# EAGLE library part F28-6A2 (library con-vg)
CONNECTOR female, 28 pins + 6 high current, type C
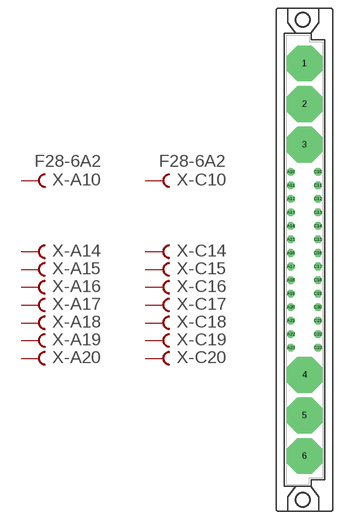
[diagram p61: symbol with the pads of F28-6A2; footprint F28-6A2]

Designator prefix X; gates -A10=FVAL -A14=FEM -A15=FEM -A16=FEM -A17=FEM -A18=FEM -A19=FEM -A20=FEM -C10=FVAL -C14=FEM -C15=FEM -C16=FEM -C17=FEM -C18=FEM -C19=FEM -C20=FEM -A21=FEM -A22=FEM -A23=FEM -C21=FEM -C22=FEM -C23=FEM -1=FEM-HIGHCUR -2=FEM-HIGHCUR -3=FEM-HIGHCUR -4=FEM-HIGHCUR -5=FEM-HIGHCUR -6=FEM-HIGHCUR -A11=FEM -A12=FEM -A13=FEM -C11=FEM -C12=FEM -C13=FEM

## F28-6A2  [F28-6A2]
1  -1:B  pas
2  -2:B  pas
3  -3:B  pas
4  -4:B  pas
5  -5:B  pas
6  -6:B  pas
A10  -A10:B  pas
A11  -A11:B  pas
A12  -A12:B  pas
A13  -A13:B  pas
A14  -A14:B  pas
A15  -A15:B  pas
A16  -A16:B  pas
A17  -A17:B  pas
A18  -A18:B  pas
A19  -A19:B  pas
A20  -A20:B  pas
A21  -A21:B  pas
A22  -A22:B  pas
A23  -A23:B  pas
C10  -C10:B  pas
C11  -C11:B  pas
C12  -C12:B  pas
C13  -C13:B  pas
C14  -C14:B  pas
C15  -C15:B  pas
C16  -C16:B  pas
C17  -C17:B  pas
C18  -C18:B  pas
C19  -C19:B  pas
C20  -C20:B  pas
C21  -C21:B  pas
C22  -C22:B  pas
C23  -C23:B  pas

## Footprint F28-6A2 (pad centres in mm)
CONNECTOR female, 28 pins + 6 high current, type C
drill 5.7 octagon: 1 0,36.83; 2 0,29.21; 3 0,21.59; 4 0,-21.59; 5 0,-29.21; 6 0,-36.83
drill 0.914 octagon: A10 -2.54,16.51; A11 -2.54,13.97; A12 -2.54,11.43; A13 -2.54,8.89; A14 -2.54,6.35; A15 -2.54,3.81; A16 -2.54,1.27; A17 -2.54,-1.27; A18 -2.54,-3.81; A19 -2.54,-6.35; A20 -2.54,-8.89; A21 -2.54,-11.43; A22 -2.54,-13.97; A23 -2.54,-16.51; C10 2.54,16.51; C11 2.54,13.97; C12 2.54,11.43; C13 2.54,8.89; C14 2.54,6.35; C15 2.54,3.81; C16 2.54,1.27; C17 2.54,-1.27; C18 2.54,-3.81; C19 2.54,-6.35; C20 2.54,-8.89; C21 2.54,-11.43; C22 2.54,-13.97; C23 2.54,-16.51
hole 2.794 at -0.305,45.009
hole 2.794 at -0.305,-45.009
